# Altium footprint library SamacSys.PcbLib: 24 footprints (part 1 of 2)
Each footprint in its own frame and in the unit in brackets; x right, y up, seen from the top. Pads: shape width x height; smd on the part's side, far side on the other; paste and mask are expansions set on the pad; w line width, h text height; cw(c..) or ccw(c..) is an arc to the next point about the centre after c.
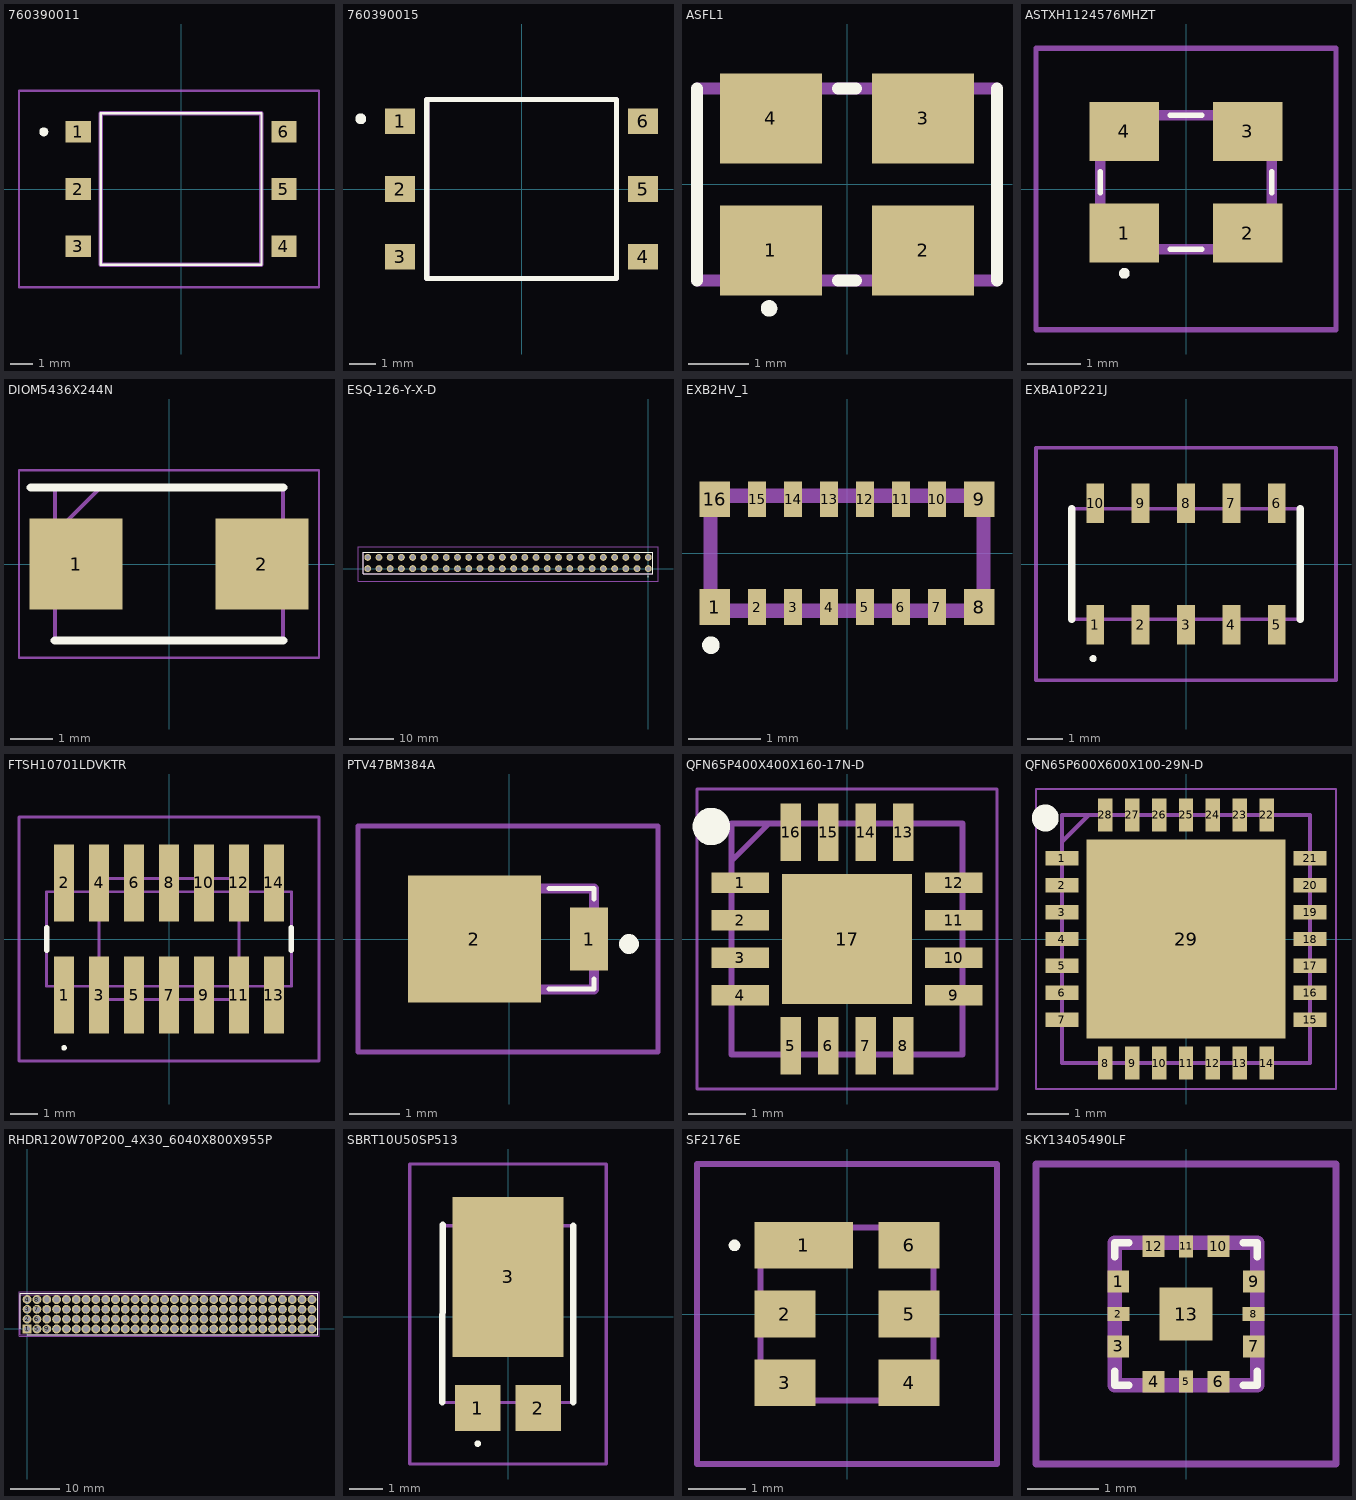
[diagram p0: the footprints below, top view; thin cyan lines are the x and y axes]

## 760390011 [mm]
pads (6):
  rect 1.12x0.96 smd: 1(-4.57,2.54) 2(-4.57,0) 3(-4.57,-2.54) 4(4.57,-2.54) 5(4.57,0) 6(4.57,2.54)
Top Overlay:
  lines w0.1: -3.57,-3.365 3.57,-3.365 3.57,3.365 -3.57,3.365 -3.57,-3.365
  lines w0.2: -6.2,2.54 cw(c-6.1,2.54) -6,2.54 cw(c-6.1,2.54) -6.2,2.54
Mechanical 13:
  lines w0.2: -3.57,-3.365 3.57,-3.365 3.57,3.365 -3.57,3.365 -3.57,-3.365
Mechanical 15:
  lines w0.1: -7.2,-4.365 6.13,-4.365 6.13,4.365 -7.2,4.365 -7.2,-4.365

## 760390015 [mm]
pads (6):
  rect 1.12x0.96 smd: 1(-4.57,2.54) 2(-4.57,0) 3(-4.57,-2.54) 4(4.57,-2.54) 5(4.57,0) 6(4.57,2.54)
Top Overlay:
  circle w0.2: c-6.049,2.64 r0.104
  lines w0.2: -3.57,-3.365 3.57,-3.365 3.57,3.365 -3.57,3.365 -3.57,-3.365
Mechanical 13:
  lines w0.2: -3.57,-3.365 -3.57,3.365 3.57,3.365 3.57,-3.365 -3.57,-3.365
3D body "760390014.stp": height 4.06, standoff 0, extent -5.005,-3.235 4.955,3.245

## ASFL1 [mm]
pads (4):
  rect 1.7x1.5 smd: 1(-1.27,-1.1) 2(1.27,-1.1) 3(1.27,1.1) 4(-1.27,1.1)
Top Overlay:
  circle w0.2: c-1.299,-2.066 r0.037
  lines w0.2: -2.5,-1.6 -2.5,1.6 ; -0.154,-1.6 0.154,-1.6 ; -0.154,1.6 0.154,1.6 ; 2.5,-1.6 2.5,1.6
Mechanical 13:
  lines w0.2: -2.5,-1.6 2.5,-1.6 2.5,1.6 -2.5,1.6 -2.5,-1.6
3D body "ASFL1-75.000MHZ-L-T.stp": height 1.29, standoff -0.01, extent -2.5,-1.6 2.5,1.6

## ASTXH1124576MHZT [mm]
pads (4):
  rect 1.3x1.1 smd: 1(-1.15,-0.825) 2(1.15,-0.825) 3(1.15,1.075) 4(-1.15,1.075)
Top Overlay:
  lines w0.1: -1.6,-0.075 -1.6,0.325 ; -0.3,-1.125 0.3,-1.125 ; -0.3,1.375 0.3,1.375 ; 1.6,-0.075 1.6,0.325 ; -1.2,-1.575 ccw(c-1.15,-1.575) -1.1,-1.575 ccw(c-1.15,-1.575) -1.2,-1.575
Mechanical 13:
  lines w0.2: -1.6,-1.125 -1.6,1.375 1.6,1.375 1.6,-1.125 -1.6,-1.125
Mechanical 15:
  lines w0.1: -2.8,-2.625 -2.8,2.625 2.8,2.625 2.8,-2.625 -2.8,-2.625
3D body "ASTX-H11-32.000MHZ-I25-T.stp": height 1.2, standoff 0, extent -1.69,-1.265 1.69,1.515

## DIOM5436X244N [mm]
pads (2):
  rect 2.2x2.15 smd: 1(-2.2,0) 2(2.2,0)
Top Overlay:
  lines w0.2: -3.275,1.81 2.7,1.81 ; -2.7,-1.81 2.7,-1.81
Mechanical 13:
  lines w0.1: -2.7,0.735 -1.625,1.81 ; -2.7,-1.81 -2.7,1.81 2.7,1.81 2.7,-1.81 -2.7,-1.81
Mechanical 15:
  lines w0.05: -3.55,-2.22 -3.55,2.22 3.55,2.22 3.55,-2.22 -3.55,-2.22
3D body "SACB50.stp": height 2.44, standoff 0, extent -2.7,-1.81 2.7,1.81

## ESQ-126-Y-X-D [mm]
pads (52):
  round 1.55 hole 1.02: 1(0,0) 2(0,2.54) 3(-2.54,0) 4(-2.54,2.54) 5(-5.08,0) 6(-5.08,2.54) 7(-7.62,0) 8(-7.62,2.54) 9(-10.16,0) 10(-10.16,2.54) 11(-12.7,0) 12(-12.7,2.54) 13(-15.24,0) 14(-15.24,2.54) 15(-17.78,0) 16(-17.78,2.54) 17(-20.32,0) 18(-20.32,2.54) 19(-22.86,0) 20(-22.86,2.54) 21(-25.4,0) 22(-25.4,2.54) 23(-27.94,0) 24(-27.94,2.54) 25(-30.48,0) 26(-30.48,2.54) 27(-33.02,0) 28(-33.02,2.54) 29(-35.56,0) 30(-35.56,2.54) 31(-38.1,0) 32(-38.1,2.54) 33(-40.64,0) 34(-40.64,2.54) 35(-43.18,0) 36(-43.18,2.54) 37(-45.72,0) 38(-45.72,2.54) 39(-48.26,0) 40(-48.26,2.54) 41(-50.8,0) 42(-50.8,2.54) 43(-53.34,0) 44(-53.34,2.54) 45(-55.88,0) 46(-55.88,2.54) 47(-58.42,0) 48(-58.42,2.54) 49(-60.96,0) 50(-60.96,2.54) 51(-63.5,0) 52(-63.5,2.54)
Top Overlay:
  circle w0.2: c-0.05,-1.75 r0.05
  lines w0.1: -64.5,-1.205 -64.5,3.745 1,3.745 1,-1.205 -64.5,-1.205
Mechanical 13:
  lines w0.2: -64.5,-1.205 -64.5,3.745 1,3.745 1,-1.205 -64.5,-1.205
Mechanical 15:
  lines w0.05: -65.7,-2.85 -65.7,4.945 2.2,4.945 2.2,-2.85 -65.7,-2.85
3D body "ESQ-126-59-G-D.stp": height 16.11, standoff -7.13, extent -64.974,-1.21 1.574,3.87

## EXB2HV_1 [mm]
pads (16):
  rect 0.425x0.5 smd: 1(-1.837,-0.75) 8(1.837,-0.75) 9(1.837,0.75) 16(-1.837,0.75)
  rect 0.25x0.5 smd: 2(-1.25,-0.75) 3(-0.75,-0.75) 4(-0.25,-0.75) 5(0.25,-0.75) 6(0.75,-0.75) 7(1.25,-0.75) 10(1.25,0.75) 11(0.75,0.75) 12(0.25,0.75) 13(-0.25,0.75) 14(-0.75,0.75) 15(-1.25,0.75)
Top Overlay:
  circle w0.2: c-1.893,-1.28 r0.022
Mechanical 13:
  lines w0.2: -1.9,-0.8 -1.9,0.8 1.9,0.8 1.9,-0.8 -1.9,-0.8
3D body "EXB-2HV181JV.stp": height 0.55, standoff 0, extent -1.95,-0.9 1.95,0.9

## EXBA10P221J [mm]
pads (10):
  rect 0.5x1.1 smd: 1(-2.54,-1.7) 2(-1.27,-1.7) 3(0,-1.7) 4(1.27,-1.7) 5(2.54,-1.7) 6(2.54,1.7) 7(1.27,1.7) 8(0,1.7) 9(-1.27,1.7) 10(-2.54,1.7)
Top Overlay:
  lines w0.1: -2.6,-2.7 ccw(c-2.6,-2.65) -2.6,-2.6 ccw(c-2.6,-2.65) -2.6,-2.7
  lines w0.2: -3.2,-1.55 -3.2,1.55 ; 3.2,-1.55 3.2,1.55
Mechanical 13:
  lines w0.1: -3.2,-1.55 -3.2,1.55 3.2,1.55 3.2,-1.55 -3.2,-1.55
Mechanical 15:
  lines w0.1: -4.2,-3.25 -4.2,3.25 4.2,3.25 4.2,-3.25 -4.2,-3.25
3D body "EXB-A10P221J.stp": height 0.75, standoff 0, extent -3.2,-2.2 3.2,2.2

## FTSH10701LDVKTR [mm]
pads (14):
  rect 0.74x2.79 smd: 1(-3.81,-2.035) 2(-3.81,2.035) 3(-2.54,-2.035) 4(-2.54,2.035) 5(-1.27,-2.035) 6(-1.27,2.035) 7(0,-2.035) 8(0,2.035) 9(1.27,-2.035) 10(1.27,2.035) 11(2.54,-2.035) 12(2.54,2.035) 13(3.81,-2.035) 14(3.81,2.035)
Top Overlay:
  lines w0.1: -3.81,-4 cw(c-3.81,-3.95) -3.81,-3.9 cw(c-3.81,-3.95) -3.81,-4
  lines w0.2: -4.445,-0.4 -4.445,0.4 ; 4.445,-0.4 4.445,0.4
Mechanical 13:
  lines w0.1: -4.445,-1.715 -4.445,1.715 4.445,1.715 4.445,-1.715 -4.445,-1.715 ; -2.54,-2.2 -2.54,2.2 2.54,2.2 2.54,-2.2 -2.54,-2.2
Mechanical 15:
  lines w0.1: -5.445,-4.43 -5.445,4.43 5.445,4.43 5.445,-4.43 -5.445,-4.43
3D body "FTSH-107-01-L-DV-K-TR.stp": height 6.12, standoff 0, extent -4.445,-2.921 4.445,2.921

## PTV47BM384A [mm]
pads (2):
  rect 0.762x1.27 smd: 1(1.602,0)
  rect 2.67x2.54 smd: 2(-0.699,0)
Top Overlay:
  lines w0.1: 0.8,-1 1.7,-1 1.7,-0.8 ; 0.8,1.015 1.7,1.015 1.7,0.8
  lines w0.2: 2.4,-0.2 ccw(c2.4,-0.1) 2.4,0 ccw(c2.4,-0.1) 2.4,-0.2
Mechanical 13:
  lines w0.2: -1.7,-1.015 -1.7,1.015 1.7,1.015 1.7,-1.015 -1.7,-1.015
Mechanical 15:
  lines w0.1: -3.034,-2.27 -3.034,2.27 2.983,2.27 2.983,-2.27 -3.034,-2.27
3D body "PTV4.7B-M3_84A.stp": height 1.02, standoff 0, extent -2.02,-1.025 1.98,1.025

## QFN65P400X400X160-17N-D [mm]
pads (17):
  rect 1x0.35 smd: 1(-1.85,0.975) 2(-1.85,0.325) 3(-1.85,-0.325) 4(-1.85,-0.975) 9(1.85,-0.975) 10(1.85,-0.325) 11(1.85,0.325) 12(1.85,0.975)
  rect 0.35x1 smd: 5(-0.975,-1.85) 6(-0.325,-1.85) 7(0.325,-1.85) 8(0.975,-1.85) 13(0.975,1.85) 14(0.325,1.85) 15(-0.325,1.85) 16(-0.975,1.85)
  rect 2.25x2.25 smd: 17(0,0)
Top Overlay:
  circle w0.325: c-2.351,1.95 r0.162
Mechanical 13:
  lines w0.1: -2,1.35 -1.35,2 ; -2,-2 -2,2 2,2 2,-2 -2,-2
Mechanical 15:
  lines w0.05: -2.6,-2.6 -2.6,2.6 2.6,2.6 2.6,-2.6 -2.6,-2.6
3D body "SKY12212-478LF.stp": height 1.6, standoff 0, extent -2.05,-2.05 2.05,2.05

## QFN65P600X600X100-29N-D [mm]
pads (29):
  rect 0.8x0.35 smd: 1(-3,1.95) 2(-3,1.3) 3(-3,0.65) 4(-3,0) 5(-3,-0.65) 6(-3,-1.3) 7(-3,-1.95) 15(3,-1.95) 16(3,-1.3) 17(3,-0.65) 18(3,0) 19(3,0.65) 20(3,1.3) 21(3,1.95)
  rect 0.35x0.8 smd: 8(-1.95,-3) 9(-1.3,-3) 10(-0.65,-3) 11(0,-3) 12(0.65,-3) 13(1.3,-3) 14(1.95,-3) 22(1.95,3) 23(1.3,3) 24(0.65,3) 25(0,3) 26(-0.65,3) 27(-1.3,3) 28(-1.95,3)
  rect 4.8x4.8 smd: 29(0,0)
Top Overlay:
  circle w0.325: c-3.401,2.925 r0.162
Mechanical 13:
  lines w0.1: -3,2.35 -2.35,3 ; -3,-3 -3,3 3,3 3,-3 -3,-3
Mechanical 15:
  lines w0.05: -3.625,-3.625 -3.625,3.625 3.625,3.625 3.625,-3.625 -3.625,-3.625
3D body "SX1278IMLTRT.stp": height 1, standoff 0, extent -3.05,-3.05 3.05,3.05

## RHDR120W70P200_4X30_6040X800X955P [mm]
pads (120):
  rect 1.8x1.8 hole 1.2: 1(0,0)
  round 1.8 hole 1.2: 2(0,2) 3(0,4) 4(0,6) 5(2,0) 6(2,2) 7(2,4) 8(2,6) 9(4,0) 10(4,2) 11(4,4) 12(4,6) 13(6,0) 14(6,2) 15(6,4) 16(6,6) 17(8,0) 18(8,2) 19(8,4) 20(8,6) 21(10,0) 22(10,2) 23(10,4) 24(10,6) 25(12,0) 26(12,2) 27(12,4) 28(12,6) 29(14,0) 30(14,2) 31(14,4) 32(14,6) 33(16,0) 34(16,2) 35(16,4) 36(16,6) 37(18,0) 38(18,2) 39(18,4) 40(18,6) 41(20,0) 42(20,2) 43(20,4) 44(20,6) 45(22,0) 46(22,2) 47(22,4) 48(22,6) 49(24,0) 50(24,2) 51(24,4) 52(24,6) 53(26,0) 54(26,2) 55(26,4) 56(26,6) 57(28,0) 58(28,2) 59(28,4) 60(28,6) 61(30,0) 62(30,2) 63(30,4) 64(30,6) 65(32,0) 66(32,2) 67(32,4) 68(32,6) 69(34,0) 70(34,2) 71(34,4) 72(34,6) 73(36,0) 74(36,2) 75(36,4) 76(36,6) 77(38,0) 78(38,2) 79(38,4) 80(38,6) 81(40,0) 82(40,2) 83(40,4) 84(40,6) 85(42,0) 86(42,2) 87(42,4) 88(42,6) 89(44,0) 90(44,2) 91(44,4) 92(44,6) 93(46,0) 94(46,2) 95(46,4) 96(46,6) 97(48,0) 98(48,2) 99(48,4) 100(48,6) 101(50,0) 102(50,2) 103(50,4) 104(50,6) 105(52,0) 106(52,2) 107(52,4) 108(52,6) 109(54,0) 110(54,2) 111(54,4) 112(54,6) 113(56,0) 114(56,2) 115(56,4) 116(56,6) 117(58,0) 118(58,2) 119(58,4) 120(58,6)
Top Overlay:
  lines w0.2: -1.4,0 -1.4,7.3 59.2,7.3 59.2,-1.2 0,-1.2
Mechanical 13:
  lines w0.1: -1.4,-1.2 59.2,-1.2 59.2,7 -1.4,7 -1.4,-1.2
Mechanical 15:
  lines w0.05: -1.65,-1.45 59.45,-1.45 59.45,7.55 -1.65,7.55 -1.65,-1.45
3D body "5P03-2021-DA.stp": height 9.55, standoff -12.6, extent -1.2,-1 59.2,7

## SBRT10U50SP513 [mm]
pads (3):
  rect 1.39x1.4 smd: 1(-0.92,-2.77) 2(0.92,-2.77)
  rect 3.36x4.86 smd: 3(0,1.212)
Top Overlay:
  lines w0.1: -0.92,-3.9 ccw(c-0.92,-3.85) -0.92,-3.8 ccw(c-0.92,-3.85) -0.92,-3.9
  lines w0.2: -2,-2.6 -1.983,2.8 ; 1.983,-2.6 1.983,2.77
Mechanical 13:
  lines w0.1: -1.983,-2.6 -1.983,2.77 1.983,2.77 1.983,-2.6 -1.983,-2.6
Mechanical 15:
  lines w0.1: -2.983,-4.47 -2.983,4.642 2.983,4.642 2.983,-4.47 -2.983,-4.47
3D body "SBRT10U50SP5-13.stp": height 1.25, standoff 0, extent -1.983,-3.331 1.983,3.306

## SF2176E [mm]
pads (6):
  rect 1.7x0.81 smd: 1(-0.75,1.19)
  rect 1.05x0.81 smd: 2(-1.075,0) 3(-1.075,-1.19) 4(1.075,-1.19) 5(1.075,0) 6(1.075,1.19)
Top Overlay:
  lines w0.1: -2,1.19 cw(c-1.95,1.19) -1.9,1.19 cw(c-1.95,1.19) -2,1.19
Mechanical 13:
  lines w0.1: -1.5,-1.5 -1.5,1.5 1.5,1.5 1.5,-1.5 -1.5,-1.5
Mechanical 15:
  lines w0.1: -2.6,-2.6 -2.6,2.6 2.6,2.6 2.6,-2.6 -2.6,-2.6
3D body "SF2176E.stp": height 1.48, standoff 0, extent -1.519,-1.514 1.519,1.514

## SKY13405490LF [mm]
pads (13):
  rect 0.3x0.31 smd: 1(-0.95,0.455) 3(-0.95,-0.455) 7(0.95,-0.455) 9(0.95,0.455)
  rect 0.31x0.2 smd: 2(-0.95,0) 8(0.95,0)
  rect 0.31x0.3 smd: 4(-0.455,-0.95) 6(0.455,-0.95) 10(0.455,0.95) 12(-0.455,0.95)
  rect 0.2x0.31 smd: 5(0,-0.95) 11(0,0.95)
  rect 0.75x0.75 smd: 13(0,0)
Top Overlay:
  lines w0.1: -1,-0.8 -1,-1 -0.8,-1 ; -1,0.8 -1,1 -0.8,1 ; 0.8,-1 1,-1 1,-0.8 ; 0.8,1 1,1 1,0.8
Mechanical 13:
  lines w0.2: -1,-1 -1,1 1,1 1,-1 -1,-1
Mechanical 15:
  lines w0.1: -2.105,-2.105 -2.105,2.105 2.105,2.105 2.105,-2.105 -2.105,-2.105
3D body "SKY13405-490LF.stp": height 1.1, standoff 0, extent -1,-1 1,1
